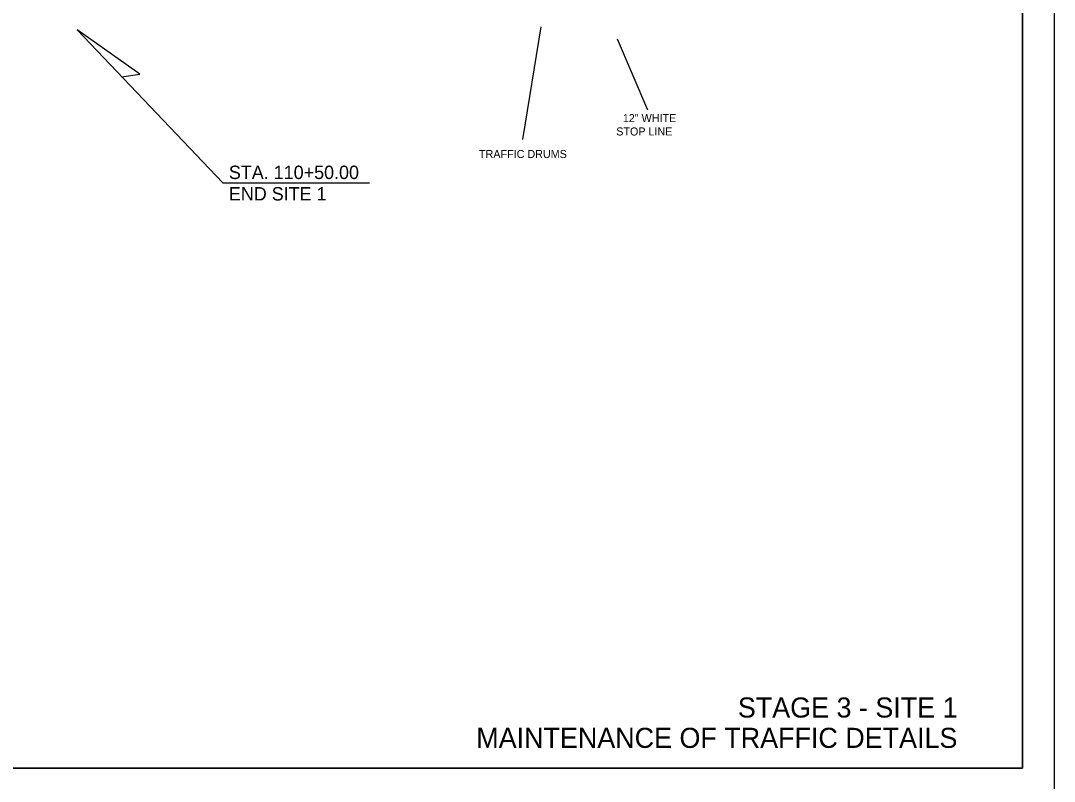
# Model space of a CAD drawing. Extents: x 1398460 to 1408037, y 380768 to 383968.
# Drawn here: x 1403228 to 1403999, y 381844 to 382412 of the extents above; entities that cross this region are included whole.
import ezdxf

# ---------------------------------------------------------------- set-up
doc = ezdxf.new("R2010")
doc.units = 0
for name, color, linetype in [('Default', 7, 'Continuous'), ('R_Border', 7, 'Continuous'), ('R_Dimension', 7, 'Continuous'), ('R_MOT', 7, 'Continuous'), ('R_No Plot', 7, 'Continuous')]:
    doc.layers.add(name, color=color, linetype=linetype)

msp = doc.modelspace()

# ---------------------------------------------------------------- linework, layer by layer
at = {"layer": 'Default'}
for p, q in [((1403269.97, 382404.82), (1403378.77, 382290.65)), ((1403378.77, 382290.65), (1403488.05, 382290.65))]:
    msp.add_line(p, q, dxfattribs=at)
msp.add_lwpolyline([(1403303.2, 382369.95), (1403316.82, 382371.82), (1403269.97, 382404.82)], dxfattribs=at)
at = {"layer": 'R_Border'}
for q in [(1403975.17, 382881.42), (1402394.27, 381854.12)]:
    msp.add_line((1403975.17, 381854.12), q, dxfattribs=at)
at = {"layer": 'R_Dimension'}
msp.add_line((1403602.42, 382323.18), (1403616.29, 382407.2), dxfattribs=at)
at = {"layer": 'R_MOT'}
msp.add_line((1403672.8, 382398.07), (1403695.37, 382345.3), dxfattribs=at)
at = {"layer": 'R_No Plot'}
for points in [[(1402332.23, 382900.89), (1403998.93, 382900.89), (1403998.93, 381834.2), (1402332.23, 381834.2)], [(1402394.27, 382881.42), (1402394.27, 381854.12), (1403975.17, 381854.12), (1403975.17, 382710.36), (1403858.52, 382710.36), (1403858.52, 382832.02), (1403661.97, 382832.02), (1403661.97, 382881.42)], [(1403563.87, 382881.42), (1403661.97, 382881.42), (1403661.97, 382832.02), (1403742.53, 382832.02), (1403858.52, 382832.02), (1403858.52, 382710.36), (1403975.17, 382710.36), (1403975.17, 381854.12), (1402394.27, 381854.12), (1402394.27, 382881.42)]]:
    msp.add_lwpolyline(points, close=True, dxfattribs=at)

# ---------------------------------------------------------------- texts
at = {"layer": 'Default'}
for s, p in [('12" WHITE', (1403677.07, 382336.03)), ('STOP LINE', (1403672.16, 382326.07))]:
    msp.add_text(s, height=6, rotation=0, dxfattribs=at).set_placement(p)
at = {"layer": 'R_Border'}
for s, height, p in [('TRAFFIC DRUMS', 6, (1403569.8, 382309.25)), ('STAGE 3 - SITE 1 ', 15, (1403762.88, 381891.76)), ('MAINTENANCE OF TRAFFIC DETAILS', 15, (1403567.77, 381869.12))]:
    msp.add_text(s, height=height, dxfattribs=at).set_placement(p)
at = {"layer": 'R_Dimension'}
for s, p in [('STA. 110+50.00', (1403383.25, 382293.57)), ('END SITE 1', (1403383.25, 382277.57))]:
    msp.add_text(s, height=10, dxfattribs=at).set_placement(p)

doc.saveas('drawing.dxf')
